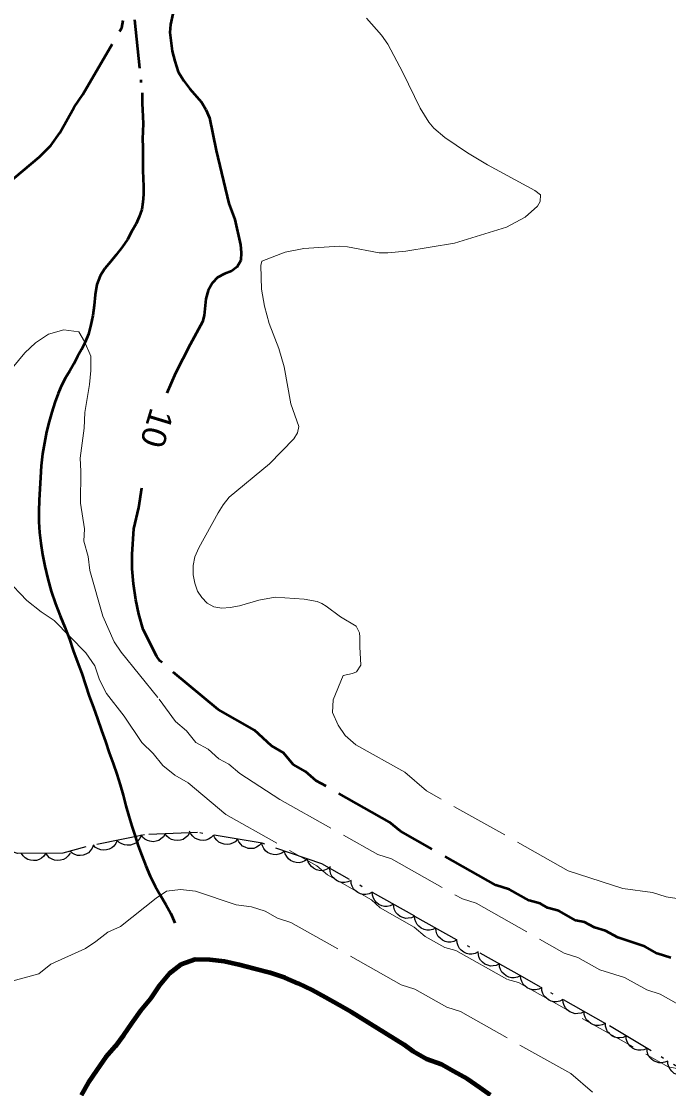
# Model space of a CAD drawing. Extents: x 355726 to 357533, y 5103782 to 5105258.
# Drawn here: x 356313.2 to 356353.2, y 5104505.8 to 5104571.7 of the extents above; entities that cross this region are included whole.
import ezdxf
from ezdxf.enums import TextEntityAlignment as Align

# ---------------------------------------------------------------- set-up
doc = ezdxf.new("R2010")
doc.units = 0
doc.header["$LTSCALE"] = 0.6
for name, pattern in [('DASH_DOUBLE_DOT', [9.2, 5, -1.2, 0.3, -1.2, 0.3, -1.2]), ('DOT_DASHED', [7.7, 5, -1.2, 0.3, -1.2]), ('LONG_DASHED', [7.5, 6, -1.5])]:
    doc.linetypes.add(name, pattern=pattern)
for name, color, linetype, lineweight in [('1', 7, 'LONG_DASHED', 53), ('2', 7, 'LONG_DASHED', 13), ('4', 7, 'DASH_DOUBLE_DOT', 53), ('44', 7, 'Continuous', 25)]:
    doc.layers.add(name, color=color, linetype=linetype, lineweight=lineweight)

msp = doc.modelspace()

# ---------------------------------------------------------------- linework, layer by layer
at = {"layer": '1'}
for points in [[(356322.71, 5104572.78), (356322.41, 5104571.46), (356322.38, 5104570.97), (356322.53, 5104569.83), (356322.68, 5104569.2), (356322.9, 5104568.55), (356323.24, 5104568), (356323.62, 5104567.5), (356324.34, 5104566.68), (356324.6, 5104566.22), (356324.82, 5104565.7), (356325.24, 5104563.7), (356326.01, 5104560.43), (356326.38, 5104559.44), (356326.74, 5104557.88), (356326.78, 5104557.4), (356326.75, 5104556.91), (356326.54, 5104556.51), (356326.19, 5104556.24), (356325.74, 5104556.08), (356325.32, 5104555.86), (356325, 5104555.53), (356324.75, 5104555.05), (356324.59, 5104554.54), (356324.49, 5104553.51), (356324.4, 5104553.13), (356323.63, 5104551.73), (356322.73, 5104549.95), (356322.19, 5104548.72)], [(356308.38, 5104557.34), (356309, 5104558.08), (356309.7, 5104558.78), (356310.93, 5104560.26), (356312.28, 5104561.58), (356314.34, 5104563.3), (356315.04, 5104564), (356315.58, 5104564.78), (356316.47, 5104566.36), (356317.01, 5104567.14), (356319.42, 5104571.27), (356319.5, 5104571.71)], [(356353.29, 5104513.88), (356352.45, 5104514.16), (356351.69, 5104514.58), (356350.01, 5104515.13), (356349.26, 5104515.56), (356348.57, 5104515.75), (356347.97, 5104516.09), (356347.43, 5104516.19), (356346.37, 5104516.79), (356345.68, 5104516.98), (356345.23, 5104517.23), (356344.54, 5104517.42), (356343.33, 5104518.1), (356342.49, 5104518.37), (356336.61, 5104521.69), (356335.94, 5104522.26), (356331.41, 5104524.81), (356330.74, 5104525.39), (356329.99, 5104525.81), (356329.4, 5104526.54), (356328.65, 5104526.96), (356327.61, 5104527.94), (356325.35, 5104529.21), (356321.76, 5104532.21), (356321.57, 5104532.48), (356320.73, 5104534.14), (356320.46, 5104535.08), (356320.27, 5104535.98), (356320.13, 5104536.96), (356320.06, 5104537.89), (356320.06, 5104538.78), (356320.15, 5104540.35), (356320.46, 5104541.67), (356320.65, 5104542.88)]]:
    msp.add_lwpolyline(points, dxfattribs=at)
at = {"layer": '2'}
for points in [[(356338.21, 5104524.18), (356336.87, 5104525.33), (356333.86, 5104527.03), (356333.19, 5104527.6), (356332.76, 5104528.24), (356332.41, 5104529.03), (356332.45, 5104529.8), (356333.07, 5104531.3), (356333.65, 5104531.42), (356333.9, 5104531.54), (356334.17, 5104531.94), (356334.1, 5104533.08), (356334.11, 5104533.67), (356334.07, 5104533.94), (356333.88, 5104534.34), (356332.9, 5104534.92), (356332.02, 5104535.59), (356331.75, 5104535.74), (356331.46, 5104535.86), (356330.67, 5104536.01), (356328.87, 5104536.13), (356327.86, 5104535.95), (356326.68, 5104535.61), (356326.09, 5104535.5), (356325.58, 5104535.45), (356325.1, 5104535.54), (356324.68, 5104535.76), (356324.35, 5104536.11), (356324.09, 5104536.5), (356323.92, 5104536.99), (356323.82, 5104537.51), (356323.82, 5104538.09), (356323.92, 5104538.63), (356324.17, 5104539.17), (356325.36, 5104541.34), (356325.66, 5104541.84), (356326.04, 5104542.3), (356328.53, 5104544.37), (356330.02, 5104545.9), (356330.26, 5104546.28), (356330.33, 5104546.67), (356329.85, 5104548.07), (356329.44, 5104550.34), (356329.1, 5104551.47), (356328.51, 5104553.01), (356328.22, 5104554.09), (356328.04, 5104555.13), (356327.99, 5104556.59), (356328.05, 5104556.86), (356329.5, 5104557.42), (356330.65, 5104557.65), (356332.83, 5104557.79), (356333.33, 5104557.74), (356335.29, 5104557.38), (356335.82, 5104557.37), (356336.94, 5104557.48), (356339.94, 5104557.97), (356343.14, 5104558.96), (356344.31, 5104559.58), (356345.07, 5104560.25), (356345.22, 5104560.55), (356345.25, 5104560.96), (356344.89, 5104561.23), (356341.98, 5104562.8), (356340.74, 5104563.55), (356339.35, 5104564.49), (356338.67, 5104565.07), (356338.36, 5104565.44), (356337.83, 5104566.3), (356336.76, 5104568.51), (356335.82, 5104570.26), (356335.43, 5104570.8), (356334.52, 5104571.86)], [(356312.25, 5104549.79), (356313.44, 5104551.2), (356314.09, 5104551.83), (356314.9, 5104552.37), (356315.84, 5104552.63), (356316.77, 5104552.5), (356317.12, 5104551.9), (356317.51, 5104551), (356317.5, 5104550.11), (356317.42, 5104549.26), (356317.14, 5104547.53), (356317.09, 5104546.57), (356316.84, 5104544.72), (356316.88, 5104543.91), (356316.86, 5104541.94), (356317.11, 5104540.36), (356317.07, 5104539.59), (356317.34, 5104538.65), (356317.45, 5104537.79), (356318.24, 5104534.97), (356318.94, 5104533.38), (356319.37, 5104532.74), (356321.71, 5104529.84), (356322.73, 5104528.47), (356323.4, 5104527.9), (356323.99, 5104527.17), (356324.74, 5104526.75), (356325.41, 5104526.17), (356326.02, 5104525.83), (356326.69, 5104525.26), (356329.17, 5104523.66), (356335.21, 5104520.26), (356336.05, 5104519.99), (356340.43, 5104517.52), (356341.27, 5104517.25), (356346.71, 5104514.18), (356347.55, 5104513.91), (356348.91, 5104513.14), (356350.44, 5104512.68), (356351.8, 5104511.91), (356352.64, 5104511.64), (356354.9, 5104510.36)], [(356312.29, 5104537.24), (356313.55, 5104535.94), (356314.44, 5104535.24), (356315.23, 5104534.7), (356317.19, 5104532.7), (356317.74, 5104531.9), (356318.04, 5104531.03), (356318.47, 5104530.2), (356319.56, 5104528.79), (356320.65, 5104527.18), (356321.35, 5104526.49), (356321.94, 5104525.76), (356322.68, 5104525.15), (356323.51, 5104524.68)], [(356323.51, 5104524.68), (356325.84, 5104522.72), (356331.44, 5104519.57), (356332.11, 5104519), (356334.83, 5104517.46), (356335.35, 5104516.97), (356337.46, 5104515.78), (356338.13, 5104515.21), (356339.34, 5104514.53), (356340.03, 5104514.34), (356343.21, 5104512.55), (356343.9, 5104512.36), (356353.12, 5104507.17), (356353.66, 5104507.06)], [(356353.93, 5104517.51), (356353, 5104517.64), (356352.16, 5104517.91), (356350.32, 5104518.16), (356346.96, 5104519.26), (356338.21, 5104524.18)], [(356348.46, 5104505.59), (356347.11, 5104506.74), (356340.31, 5104510.57), (356339.46, 5104510.85), (356337.5, 5104511.95), (356336.66, 5104512.23), (356329.85, 5104516.06), (356329.01, 5104516.34), (356328.25, 5104516.76), (356327.41, 5104517.04), (356326.48, 5104517.16), (356323.96, 5104517.99), (356323.03, 5104518.11), (356322.17, 5104518), (356321.53, 5104517.57), (356319.34, 5104515.82), (356318.55, 5104515.47), (356317.82, 5104514.89), (356317.17, 5104514.46), (356315.03, 5104513.49), (356314.3, 5104512.9), (356312.41, 5104512.38)]]:
    msp.add_lwpolyline(points, dxfattribs=at)
at = {"layer": '4'}
for points in [[(356320.2, 5104571.76), (356320.66, 5104567.26), (356320.67, 5104566.95), (356320.67, 5104566.59)], [(356320.67, 5104566.59), (356320.7, 5104566.21), (356320.72, 5104565.78), (356320.73, 5104565.34), (356320.71, 5104564.88), (356320.7, 5104564.4), (356320.72, 5104563.92), (356320.72, 5104563.42), (356320.72, 5104562.95), (356320.72, 5104562.46), (356320.74, 5104561.96), (356320.75, 5104561.47), (356320.76, 5104560.98), (356320.71, 5104560.5), (356320.64, 5104560.05), (356320.49, 5104559.61), (356320.29, 5104559.17), (356320.04, 5104558.71), (356319.77, 5104558.2), (356319.43, 5104557.72), (356319.06, 5104557.26), (356318.72, 5104556.83), (356318.37, 5104556.41), (356318.08, 5104555.95), (356317.87, 5104555.42), (356317.78, 5104554.78), (356317.71, 5104554.12), (356317.62, 5104553.51), (356317.51, 5104552.94), (356317.35, 5104552.37), (356317.16, 5104551.86), (356316.92, 5104551.41), (356316.69, 5104550.98), (356316.45, 5104550.54), (356316.2, 5104550.09), (356315.94, 5104549.66), (356315.69, 5104549.2), (356315.48, 5104548.7), (356315.29, 5104548.15), (356315.1, 5104547.55), (356314.93, 5104546.97), (356314.76, 5104546.34), (356314.64, 5104545.66), (356314.52, 5104544.97), (356314.43, 5104544.24), (356314.39, 5104543.51), (356314.35, 5104542.82), (356314.32, 5104542.13), (356314.3, 5104541.44), (356314.3, 5104540.78), (356314.33, 5104540.12), (356314.41, 5104539.47), (356314.52, 5104538.76), (356314.67, 5104538.04), (356314.85, 5104537.26), (356315.05, 5104536.5), (356315.32, 5104535.72), (356315.61, 5104534.99), (356315.89, 5104534.28), (356316.18, 5104533.55), (356316.42, 5104532.84), (356316.69, 5104532.13), (356316.94, 5104531.42), (356317.18, 5104530.73), (356317.4, 5104530.03), (356317.66, 5104529.33), (356317.92, 5104528.63), (356318.17, 5104527.91), (356318.4, 5104527.23), (356318.64, 5104526.53), (356318.88, 5104525.87), (356319.11, 5104525.22), (356319.31, 5104524.55), (356319.49, 5104523.92), (356319.66, 5104523.26), (356319.84, 5104522.62), (356320.04, 5104522.01), (356320.23, 5104521.4), (356320.43, 5104520.79), (356320.64, 5104520.19), (356320.89, 5104519.57), (356321.16, 5104518.93), (356321.48, 5104518.3), (356321.81, 5104517.73), (356322.12, 5104517.17), (356322.43, 5104516.63), (356322.68, 5104516.04)]]:
    msp.add_lwpolyline(points, dxfattribs=at)
at = {"layer": '4', "linetype": 'Continuous', "lineweight": 90}
for points in [[(356342.16, 5104505.41), (356341.52, 5104505.87), (356340.73, 5104506.42), (356339.9, 5104506.88), (356339.14, 5104507.31), (356338.22, 5104507.63), (356337.39, 5104508.1), (356336.83, 5104508.51), (356333.58, 5104510.54), (356332.83, 5104510.96), (356331.99, 5104511.43), (356331.16, 5104511.9), (356330.29, 5104512.3), (356329.49, 5104512.65), (356328.57, 5104512.96), (356327.61, 5104513.21), (356326.65, 5104513.45), (356325.76, 5104513.65), (356324.84, 5104513.77), (356323.94, 5104513.78), (356323.07, 5104513.48), (356322.34, 5104512.89), (356321.72, 5104512.15), (356321.18, 5104511.36), (356320.56, 5104510.62), (356320.01, 5104509.83), (356319.51, 5104509.12), (356319.01, 5104508.41), (356318.43, 5104507.75), (356317.88, 5104506.96), (356317.34, 5104506.17)], [(356317.34, 5104506.17), (356316.91, 5104505.42)]]:
    msp.add_lwpolyline(points, dxfattribs=at)
at = {"layer": '44', "linetype": 'DOT_DASHED'}
for points in [[(356324.08, 5104521.62), (356320.81, 5104521.48), (356317.2, 5104520.73), (356315.78, 5104520.34), (356312.98, 5104520.33), (356309.92, 5104521.26), (356304.15, 5104523.72), (356301.33, 5104526.49), (356300.03, 5104528.42), (356298.47, 5104531.28), (356295.56, 5104535.3), (356292.88, 5104537.6), (356289.42, 5104539.94), (356286.14, 5104542.58), (356282.42, 5104545.87), (356279.13, 5104548.51), (356270.88, 5104554.34), (356265.18, 5104558.34), (356259.14, 5104561.75)], [(356414.39, 5104466.41), (356412.36, 5104469.15), (356408.54, 5104473.68), (356406.37, 5104476.88), (356403.99, 5104479.02), (356396.6, 5104483.57), (356390.39, 5104486.68), (356385.38, 5104489.1), (356380.37, 5104491.52), (356376.74, 5104493.56), (356371, 5104496.79), (356363.44, 5104501.05), (356359.99, 5104503.39), (356349.28, 5104509.82), (356344.14, 5104512.71), (356337.49, 5104516.45), (356331.75, 5104519.68), (356328.08, 5104520.95), (356324.08, 5104521.62)]]:
    msp.add_lwpolyline(points, dxfattribs=at)
at = {"layer": '44'}
for points in [[(356325.08, 5104521.45), (356324.93, 5104521.3), (356324.76, 5104521.2), (356324.6, 5104521.14), (356324.43, 5104521.12), (356324.24, 5104521.14), (356324.06, 5104521.2), (356323.92, 5104521.27), (356323.79, 5104521.39), (356323.67, 5104521.54), (356323.6, 5104521.7)], [(356319.13, 5104521.13), (356319.05, 5104520.94), (356318.92, 5104520.78), (356318.8, 5104520.67), (356318.64, 5104520.59), (356318.47, 5104520.54), (356318.28, 5104520.53), (356318.11, 5104520.54), (356317.95, 5104520.6), (356317.79, 5104520.7), (356317.66, 5104520.83)], [(356320.6, 5104521.44), (356320.52, 5104521.24), (356320.39, 5104521.09), (356320.27, 5104520.97), (356320.11, 5104520.89), (356319.94, 5104520.84), (356319.75, 5104520.83), (356319.58, 5104520.85), (356319.42, 5104520.91), (356319.26, 5104521.01), (356319.13, 5104521.13)], [(356322.09, 5104521.53), (356321.98, 5104521.36), (356321.83, 5104521.22), (356321.69, 5104521.13), (356321.53, 5104521.08), (356321.34, 5104521.05), (356321.15, 5104521.08), (356320.99, 5104521.12), (356320.84, 5104521.21), (356320.7, 5104521.33), (356320.6, 5104521.47)], [(356323.59, 5104521.6), (356323.48, 5104521.42), (356323.33, 5104521.29), (356323.19, 5104521.19), (356323.03, 5104521.14), (356322.84, 5104521.12), (356322.65, 5104521.14), (356322.49, 5104521.18), (356322.34, 5104521.27), (356322.2, 5104521.39), (356322.09, 5104521.53)], [(356326.56, 5104521.21), (356326.41, 5104521.05), (356326.24, 5104520.95), (356326.08, 5104520.89), (356325.91, 5104520.88), (356325.72, 5104520.89), (356325.54, 5104520.95), (356325.4, 5104521.02), (356325.27, 5104521.14), (356325.15, 5104521.29), (356325.08, 5104521.45)], [(356328.04, 5104520.96), (356327.89, 5104520.81), (356327.72, 5104520.71), (356327.56, 5104520.64), (356327.39, 5104520.63), (356327.2, 5104520.64), (356327.02, 5104520.71), (356326.87, 5104520.77), (356326.75, 5104520.89), (356326.63, 5104521.04), (356326.56, 5104521.21)], [(356317.66, 5104520.86), (356317.59, 5104520.66), (356317.47, 5104520.49), (356317.36, 5104520.37), (356317.2, 5104520.28), (356317.03, 5104520.22), (356316.84, 5104520.2), (356316.68, 5104520.2), (356316.51, 5104520.26), (356316.35, 5104520.34), (356316.21, 5104520.46)], [(356329.46, 5104520.47), (356329.29, 5104520.35), (356329.1, 5104520.28), (356328.94, 5104520.24), (356328.76, 5104520.26), (356328.58, 5104520.3), (356328.41, 5104520.39), (356328.28, 5104520.49), (356328.17, 5104520.63), (356328.09, 5104520.79), (356328.04, 5104520.96)], [(356330.87, 5104519.98), (356330.71, 5104519.86), (356330.52, 5104519.79), (356330.35, 5104519.75), (356330.18, 5104519.77), (356330, 5104519.81), (356329.83, 5104519.9), (356329.7, 5104520), (356329.59, 5104520.14), (356329.5, 5104520.3), (356329.46, 5104520.47)], [(356314.72, 5104520.34), (356314.61, 5104520.16), (356314.45, 5104520.03), (356314.31, 5104519.95), (356314.14, 5104519.9), (356313.96, 5104519.89), (356313.77, 5104519.92), (356313.61, 5104519.96), (356313.46, 5104520.06), (356313.33, 5104520.18), (356313.22, 5104520.33)], [(356316.22, 5104520.34), (356316.11, 5104520.17), (356315.95, 5104520.04), (356315.81, 5104519.95), (356315.64, 5104519.91), (356315.46, 5104519.89), (356315.27, 5104519.92), (356315.11, 5104519.97), (356314.96, 5104520.06), (356314.83, 5104520.19), (356314.72, 5104520.34)], [(356332.29, 5104519.49), (356332.12, 5104519.37), (356331.93, 5104519.3), (356331.77, 5104519.26), (356331.6, 5104519.28), (356331.42, 5104519.32), (356331.25, 5104519.41), (356331.11, 5104519.51), (356331.01, 5104519.65), (356330.92, 5104519.81), (356330.87, 5104519.98)], [(356333.56, 5104518.66), (356333.37, 5104518.57), (356333.17, 5104518.54), (356333, 5104518.53), (356332.83, 5104518.57), (356332.67, 5104518.65), (356332.52, 5104518.77), (356332.4, 5104518.89), (356332.32, 5104519.04), (356332.26, 5104519.22), (356332.25, 5104519.4)], [(356334.86, 5104517.93), (356334.68, 5104517.83), (356334.48, 5104517.8), (356334.31, 5104517.79), (356334.14, 5104517.84), (356333.97, 5104517.92), (356333.82, 5104518.04), (356333.71, 5104518.15), (356333.63, 5104518.31), (356333.57, 5104518.48), (356333.56, 5104518.66)], [(356336.17, 5104517.19), (356335.98, 5104517.1), (356335.78, 5104517.06), (356335.62, 5104517.06), (356335.45, 5104517.1), (356335.28, 5104517.18), (356335.13, 5104517.3), (356335.02, 5104517.42), (356334.94, 5104517.57), (356334.88, 5104517.75), (356334.86, 5104517.93)], [(356337.48, 5104516.46), (356337.29, 5104516.36), (356337.09, 5104516.33), (356336.93, 5104516.32), (356336.76, 5104516.37), (356336.59, 5104516.44), (356336.44, 5104516.56), (356336.32, 5104516.68), (356336.24, 5104516.84), (356336.19, 5104517.01), (356336.17, 5104517.19)], [(356338.79, 5104515.72), (356338.6, 5104515.63), (356338.4, 5104515.59), (356338.23, 5104515.59), (356338.06, 5104515.63), (356337.89, 5104515.71), (356337.75, 5104515.83), (356337.63, 5104515.94), (356337.55, 5104516.1), (356337.49, 5104516.28), (356337.48, 5104516.46)], [(356340.09, 5104514.99), (356339.91, 5104514.89), (356339.71, 5104514.86), (356339.54, 5104514.85), (356339.37, 5104514.9), (356339.2, 5104514.97), (356339.05, 5104515.09), (356338.94, 5104515.21), (356338.86, 5104515.37), (356338.8, 5104515.54), (356338.79, 5104515.72)], [(356341.4, 5104514.25), (356341.21, 5104514.16), (356341.01, 5104514.12), (356340.85, 5104514.12), (356340.68, 5104514.16), (356340.51, 5104514.24), (356340.36, 5104514.36), (356340.25, 5104514.47), (356340.16, 5104514.63), (356340.11, 5104514.81), (356340.09, 5104514.99)], [(356342.71, 5104513.52), (356342.52, 5104513.42), (356342.32, 5104513.39), (356342.16, 5104513.38), (356341.99, 5104513.43), (356341.82, 5104513.5), (356341.67, 5104513.62), (356341.55, 5104513.74), (356341.47, 5104513.89), (356341.42, 5104514.07), (356341.4, 5104514.25)], [(356344.02, 5104512.78), (356343.83, 5104512.69), (356343.63, 5104512.65), (356343.46, 5104512.65), (356343.29, 5104512.69), (356343.12, 5104512.77), (356342.98, 5104512.89), (356342.86, 5104513), (356342.78, 5104513.16), (356342.72, 5104513.34), (356342.71, 5104513.52)], [(356345.32, 5104512.05), (356345.14, 5104511.95), (356344.94, 5104511.92), (356344.77, 5104511.91), (356344.6, 5104511.96), (356344.43, 5104512.03), (356344.28, 5104512.15), (356344.17, 5104512.27), (356344.09, 5104512.42), (356344.03, 5104512.6), (356344.02, 5104512.78)], [(356346.63, 5104511.31), (356346.44, 5104511.22), (356346.24, 5104511.18), (356346.08, 5104511.18), (356345.91, 5104511.22), (356345.74, 5104511.3), (356345.59, 5104511.42), (356345.48, 5104511.53), (356345.39, 5104511.69), (356345.34, 5104511.87), (356345.32, 5104512.05)], [(356347.94, 5104510.57), (356347.75, 5104510.48), (356347.55, 5104510.45), (356347.39, 5104510.44), (356347.22, 5104510.49), (356347.05, 5104510.56), (356346.9, 5104510.68), (356346.78, 5104510.8), (356346.7, 5104510.95), (356346.65, 5104511.13), (356346.63, 5104511.31)], [(356349.25, 5104509.84), (356349.06, 5104509.75), (356348.86, 5104509.71), (356348.69, 5104509.71), (356348.52, 5104509.75), (356348.35, 5104509.83), (356348.21, 5104509.95), (356348.09, 5104510.06), (356348.01, 5104510.22), (356347.95, 5104510.4), (356347.94, 5104510.57)], [(356350.53, 5104509.07), (356350.34, 5104508.98), (356350.14, 5104508.95), (356349.98, 5104508.95), (356349.81, 5104509), (356349.64, 5104509.08), (356349.5, 5104509.21), (356349.38, 5104509.32), (356349.31, 5104509.48), (356349.26, 5104509.66), (356349.25, 5104509.84)], [(356351.82, 5104508.3), (356351.63, 5104508.21), (356351.43, 5104508.18), (356351.26, 5104508.18), (356351.09, 5104508.23), (356350.93, 5104508.31), (356350.78, 5104508.43), (356350.67, 5104508.55), (356350.59, 5104508.71), (356350.54, 5104508.89), (356350.53, 5104509.07)], [(356353.1, 5104507.52), (356352.91, 5104507.44), (356352.71, 5104507.41), (356352.55, 5104507.41), (356352.38, 5104507.46), (356352.21, 5104507.54), (356352.07, 5104507.66), (356351.96, 5104507.78), (356351.88, 5104507.94), (356351.83, 5104508.12), (356351.82, 5104508.3)], [(356354.39, 5104506.75), (356354.2, 5104506.66), (356354, 5104506.64), (356353.83, 5104506.63), (356353.67, 5104506.68), (356353.5, 5104506.76), (356353.35, 5104506.89), (356353.24, 5104507.01), (356353.17, 5104507.17), (356353.11, 5104507.34), (356353.1, 5104507.52)]]:
    msp.add_lwpolyline(points, dxfattribs=at)

# ---------------------------------------------------------------- texts
at = {"layer": '1', "width": 1.05}
msp.add_text('10', height=1.5, rotation=253.116, dxfattribs=at).set_placement((356320.863, 5104546.778), align=Align.CENTER)

doc.saveas('drawing.dxf')
